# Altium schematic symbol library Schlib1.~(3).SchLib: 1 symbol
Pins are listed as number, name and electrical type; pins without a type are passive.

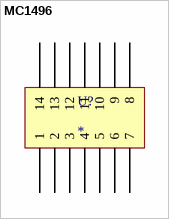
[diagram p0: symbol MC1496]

## MC1496
designator U?
pins: 1, 2, 3, 4, 5, 6, 7, 8, 9, 10, 11, 12, 13, 14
